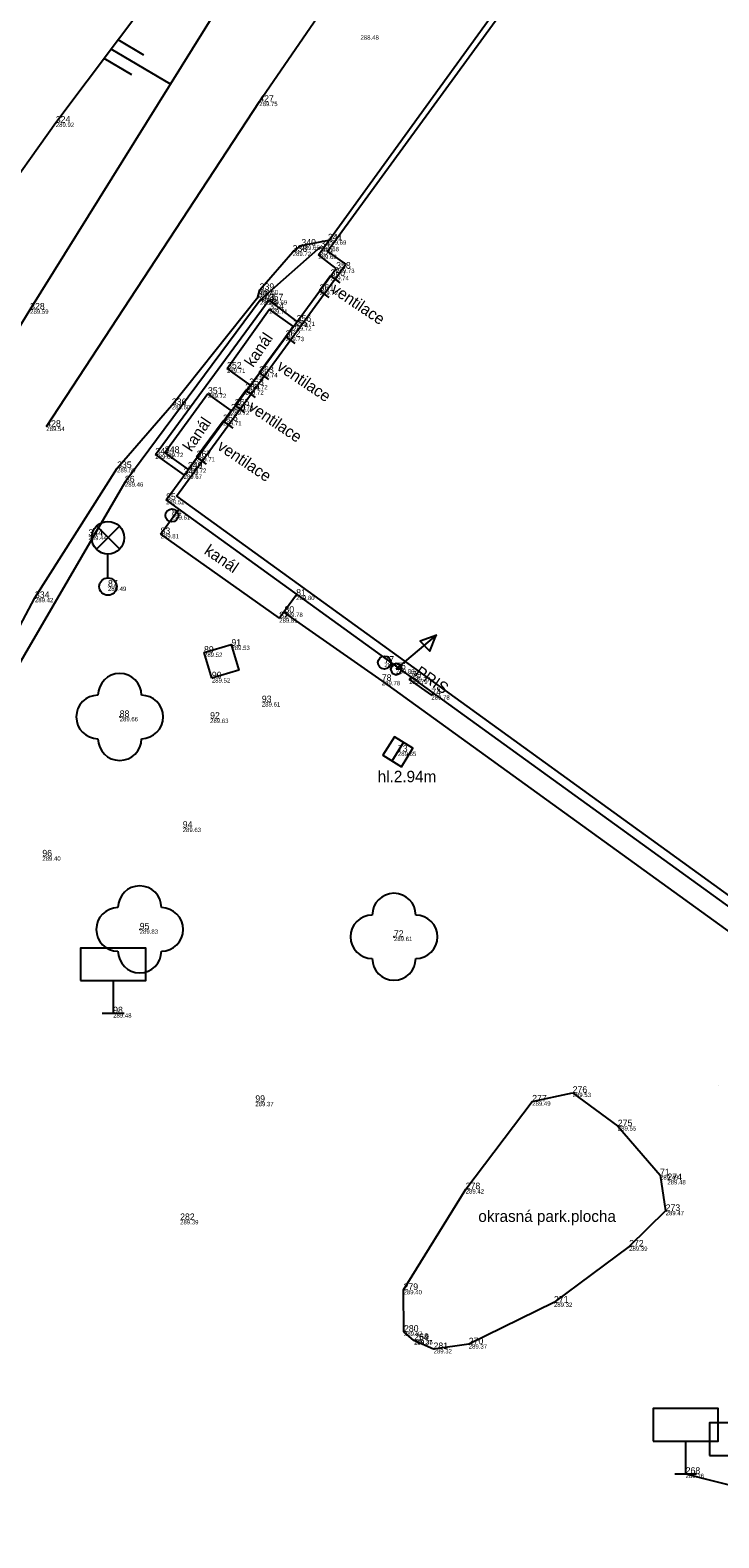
# Model space of a CAD drawing. Extents: x -805057 to -804930, y -994399 to -994240.
# Drawn here: x -805033.55 to -805017.71, y -994342.6 to -994307.89 of the extents above; entities that cross this region are included whole.
import ezdxf

# ---------------------------------------------------------------- set-up
doc = ezdxf.new("R2010")
doc.units = 0
for name, color, linetype in [('bod cislo', 7, 'Continuous'), ('bod pozice', 7, 'Continuous'), ('bod výška', 7, 'Continuous'), ('budova', 7, 'Continuous'), ('kanalizace', 7, 'Continuous'), ('Katastralni mapa', 7, 'Continuous'), ('komunikace', 7, 'Continuous'), ('lampa', 7, 'Continuous'), ('označník', 7, 'Continuous'), ('plot', 7, 'Continuous'), ('popis', 7, 'Continuous'), ('PRIS', 7, 'Continuous'), ('strom', 7, 'Continuous'), ('svah', 7, 'Continuous'), ('svod', 7, 'Continuous'), ('zemnění', 7, 'Continuous'), ('šachta hranatá', 7, 'Continuous'), ('šrafy', 7, 'Continuous')]:
    doc.layers.add(name, color=color, linetype=linetype)

msp = doc.modelspace()

# ---------------------------------------------------------------- linework, layer by layer
at = {"layer": 'bod pozice'}
for p, q in [((-805028.28, -994309.54), (-805028.28, -994309.54)), ((-805032.96, -994310.02), (-805032.96, -994310.02)), ((-805027.31, -994312.85), (-805027.31, -994312.85)), ((-805026.87, -994312.88), (-805026.87, -994312.88)), ((-805026.7, -994312.73), (-805026.7, -994312.73)), ((-805027.51, -994312.99), (-805027.51, -994312.99)), ((-805026.92, -994313.06), (-805026.92, -994313.06)), ((-805026.64, -994313.55), (-805026.64, -994313.55)), ((-805026.51, -994313.38), (-805026.51, -994313.38)), ((-805028.27, -994313.87), (-805028.27, -994313.87)), ((-805026.89, -994313.89), (-805026.89, -994313.89)), ((-805028.31, -994314.04), (-805028.31, -994314.04)), ((-805028.26, -994314.11), (-805028.26, -994314.11)), ((-805028.06, -994314.11), (-805028.06, -994314.11)), ((-805033.55, -994314.32), (-805033.55, -994314.32)), ((-805028.05, -994314.32), (-805028.05, -994314.32)), ((-805027.42, -994314.6), (-805027.42, -994314.6)), ((-805027.67, -994314.95), (-805027.67, -994314.95)), ((-805027.5, -994314.71), (-805027.5, -994314.71)), ((-805029.02, -994315.68), (-805029.02, -994315.68)), ((-805028.28, -994315.78), (-805028.28, -994315.78)), ((-805029.46, -994316.26), (-805029.46, -994316.26)), ((-805028.6, -994316.18), (-805028.6, -994316.18)), ((-805028.51, -994316.06), (-805028.51, -994316.06)), ((-805030.29, -994316.52), (-805030.29, -994316.52)), ((-805028.93, -994316.65), (-805028.93, -994316.65)), ((-805028.84, -994316.53), (-805028.84, -994316.53)), ((-805033.18, -994317.02), (-805033.18, -994317.02)), ((-805029.11, -994316.89), (-805029.11, -994316.89)), ((-805030.67, -994317.66), (-805030.67, -994317.66)), ((-805030.45, -994317.62), (-805030.45, -994317.62)), ((-805029.72, -994317.72), (-805029.72, -994317.72)), ((-805031.55, -994317.97), (-805031.55, -994317.97)), ((-805029.92, -994317.98), (-805029.92, -994317.98)), ((-805031.37, -994318.3), (-805031.37, -994318.3)), ((-805030.02, -994318.12), (-805030.02, -994318.12)), ((-805030.423, -994318.705), (-805030.423, -994318.705)), ((-805030.29, -994319.06), (-805030.29, -994319.06)), ((-805032.21, -994319.53), (-805032.21, -994319.53)), ((-805030.55, -994319.49), (-805030.55, -994319.49)), ((-805031.76, -994320.7), (-805031.76, -994320.7)), ((-805033.44, -994320.96), (-805033.44, -994320.96)), ((-805027.43, -994320.91), (-805027.43, -994320.91)), ((-805027.82, -994321.43), (-805027.82, -994321.43)), ((-805027.7, -994321.3), (-805027.7, -994321.3)), ((-805029.55, -994322.22), (-805029.55, -994322.22)), ((-805028.92, -994322.06), (-805028.92, -994322.06)), ((-805025.4, -994322.45), (-805025.4, -994322.45)), ((-805025.13, -994322.6), (-805025.13, -994322.6)), ((-805029.37, -994322.81), (-805029.37, -994322.81)), ((-805025.46, -994322.87), (-805025.46, -994322.87)), ((-805024.83, -994322.84), (-805024.83, -994322.84)), ((-805024.77, -994322.79), (-805024.77, -994322.79)), ((-805024.32, -994323.2), (-805024.32, -994323.2)), ((-805028.22, -994323.36), (-805028.22, -994323.36)), ((-805031.49, -994323.7), (-805031.49, -994323.7)), ((-805029.41, -994323.74), (-805029.41, -994323.74)), ((-805025.09, -994324.5), (-805025.09, -994324.5)), ((-805030.04, -994326.25), (-805030.04, -994326.25)), ((-805033.27, -994326.91), (-805033.27, -994326.91)), ((-805031.03, -994328.59), (-805031.03, -994328.59)), ((-805025.18, -994328.76), (-805025.18, -994328.76)), ((-805031.64, -994330.52), (-805031.64, -994330.52)), ((-805017.71, -994332.19), (-805017.71, -994332.19)), ((-805028.37, -994332.56), (-805028.37, -994332.56)), ((-805022, -994332.55), (-805022, -994332.55)), ((-805021.07, -994332.35), (-805021.07, -994332.35)), ((-805020.03, -994333.12), (-805020.03, -994333.12)), ((-805019.06, -994334.25), (-805019.06, -994334.25)), ((-805018.89, -994334.36), (-805018.89, -994334.36)), ((-805023.53, -994334.57), (-805023.53, -994334.57)), ((-805018.93, -994335.07), (-805018.93, -994335.07)), ((-805030.1, -994335.28), (-805030.1, -994335.28)), ((-805019.77, -994335.89), (-805019.77, -994335.89)), ((-805024.96, -994336.89), (-805024.96, -994336.89)), ((-805021.5, -994337.18), (-805021.5, -994337.18)), ((-805024.95, -994337.85), (-805024.95, -994337.85)), ((-805024.72, -994338.05), (-805024.72, -994338.05)), ((-805024.71, -994338.04), (-805024.71, -994338.04)), ((-805023.46, -994338.14), (-805023.46, -994338.14)), ((-805024.27, -994338.25), (-805024.27, -994338.25)), ((-805018.47, -994341.12), (-805018.47, -994341.12))]:
    msp.add_line(p, q, dxfattribs=at)
at = {"layer": 'budova'}
for p, q in [((-805026.92, -994313.06), (-805021.089, -994305.009)), ((-805026.51, -994313.38), (-805026.92, -994313.06)), ((-805030.423, -994318.705), (-805026.51, -994313.38)), ((-804995.51, -994343.96), (-805030.423, -994318.706))]:
    msp.add_line(p, q, dxfattribs=at)
at = {"layer": 'kanalizace'}
msp.add_line((-805025.222, -994324.712), (-805024.958, -994324.288), dxfattribs=at)
msp.add_lwpolyline([(-805025.01, -994324.845), (-805024.744, -994324.421), (-805025.17, -994324.155), (-805025.435, -994324.579)], close=True, dxfattribs=at)
at = {"layer": 'Katastralni mapa'}
for points in [[(-805026.71, -994312.98), (-805021.06, -994305.21)], [(-805026.29, -994313.28), (-805026.71, -994312.98)], [(-805030.18, -994318.62), (-805026.29, -994313.28)], [(-805030.18, -994318.62), (-804995.54, -994343.69)]]:
    msp.add_lwpolyline(points, dxfattribs=at)
at = {"layer": 'komunikace'}
for p, q in [((-805028.28, -994309.54), (-805022, -994300.4)), ((-805033.55, -994314.32), (-805029.27, -994307.45)), ((-805028.28, -994309.54), (-805033.18, -994317.02)), ((-805027.51, -994312.99), (-805027.31, -994312.85)), ((-805027.31, -994312.85), (-805026.678, -994312.726)), ((-805028.27, -994313.87), (-805027.51, -994312.99)), ((-805028.31, -994314.04), (-805028.27, -994313.87)), ((-805030.67, -994317.66), (-805028.06, -994314.11)), ((-805030.29, -994316.52), (-805028.31, -994314.04)), ((-805028.06, -994314.11), (-805027.411, -994314.607)), ((-805036.691, -994319.454), (-805033.55, -994314.32)), ((-805031.55, -994317.97), (-805030.29, -994316.52)), ((-805030.002, -994318.132), (-805030.67, -994317.66)), ((-805033.44, -994320.96), (-805031.55, -994317.97)), ((-805030.55, -994319.49), (-805030.133, -994318.916)), ((-805030.55, -994319.49), (-805027.82, -994321.43)), ((-805036.91, -994327.47), (-805033.44, -994320.96)), ((-805027.82, -994321.43), (-805027.42, -994320.878)), ((-805027.7, -994321.3), (-805025.46, -994322.87)), ((-805025.46, -994322.87), (-805005.97, -994336.96))]:
    msp.add_line(p, q, dxfattribs=at)
at = {"layer": 'lampa'}
for p, q in [((-805032.024, -994319.838), (-805031.496, -994319.31)), ((-805031.488, -994319.835), (-805032.016, -994319.306)), ((-805031.76, -994320.5), (-805031.76, -994319.95))]:
    msp.add_line(p, q, dxfattribs=at)
for centre, radius in [((-805031.76, -994319.575), 0.375), ((-805031.76, -994320.7), 0.2)]:
    msp.add_circle(centre, radius, dxfattribs=at)
at = {"layer": 'označník'}
for p, q in [((-805031.64, -994329.77), (-805031.64, -994330.52)), ((-805031.89, -994330.52), (-805031.39, -994330.52)), ((-805018.47, -994340.37), (-805018.47, -994341.12)), ((-805018.72, -994341.12), (-805018.22, -994341.12)), ((-805018.47, -994341.12), (-805017.17, -994341.45))]:
    msp.add_line(p, q, dxfattribs=at)
for points in [[(-805032.39, -994329.77), (-805030.89, -994329.77), (-805030.89, -994329.02), (-805032.39, -994329.02)], [(-805019.22, -994340.37), (-805017.72, -994340.37), (-805017.72, -994339.62), (-805019.22, -994339.62)], [(-805017.92, -994340.7), (-805016.42, -994340.7), (-805016.42, -994339.95), (-805017.92, -994339.95)]]:
    msp.add_lwpolyline(points, close=True, dxfattribs=at)
at = {"layer": 'plot'}
for p, q in [((-805026.87, -994312.88), (-805028.26, -994314.11)), ((-805028.26, -994314.11), (-805031.37, -994318.3)), ((-805031.37, -994318.3), (-805035.75, -994325.82))]:
    msp.add_line(p, q, dxfattribs=at)
at = {"layer": 'PRIS'}
for p, q in [((-805024.83, -994322.84), (-805024.787, -994322.782)), ((-805024.83, -994322.84), (-805024.32, -994323.2)), ((-805024.32, -994323.2), (-805024.282, -994323.148))]:
    msp.add_line(p, q, dxfattribs=at)
at = {"layer": 'strom'}
for p, q in [((-805023.53, -994334.57), (-805022, -994332.55)), ((-805022, -994332.55), (-805021.07, -994332.35)), ((-805021.07, -994332.35), (-805020.03, -994333.12)), ((-805020.03, -994333.12), (-805019.06, -994334.25)), ((-805019.06, -994334.25), (-805018.93, -994335.07)), ((-805024.96, -994336.89), (-805023.53, -994334.57)), ((-805018.93, -994335.07), (-805019.77, -994335.89)), ((-805019.77, -994335.89), (-805021.5, -994337.18)), ((-805024.95, -994337.85), (-805024.96, -994336.89)), ((-805021.5, -994337.18), (-805023.46, -994338.14)), ((-805024.72, -994338.05), (-805024.95, -994337.85)), ((-805024.27, -994338.25), (-805024.72, -994338.05)), ((-805023.46, -994338.14), (-805024.27, -994338.25))]:
    msp.add_line(p, q, dxfattribs=at)
for centre in [(-805031.49, -994323.7), (-805031.03, -994328.59), (-805025.18, -994328.76)]:
    msp.add_circle(centre, 0.0005, dxfattribs=at)
for centre, start, end in [((-805031.49, -994323.2), 0, 180), ((-805031.99, -994323.7), 90, 270), ((-805030.99, -994323.7), 270, 90), ((-805031.49, -994324.2), 180, 360), ((-805031.03, -994328.09), 0, 180), ((-805025.18, -994328.26), 0, 180), ((-805031.53, -994328.59), 90, 270), ((-805030.53, -994328.59), 270, 90), ((-805025.68, -994328.76), 90, 270), ((-805024.68, -994328.76), 270, 90), ((-805031.03, -994329.09), 180, 360), ((-805025.18, -994329.26), 180, 360)]:
    msp.add_arc(centre, 0.5, start, end, dxfattribs=at)
at = {"layer": 'svah'}
for p, q in [((-805032.96, -994310.02), (-805030.42, -994306.63)), ((-805036.52, -994315.02), (-805032.96, -994310.02))]:
    msp.add_line(p, q, dxfattribs=at)
at = {"layer": 'svod'}
for centre in [(-805030.29, -994319.06), (-805025.4, -994322.45)]:
    msp.add_circle(centre, 0.15, dxfattribs=at)
at = {"layer": 'zemnění'}
msp.add_line((-805025.13, -994322.6), (-805024.246, -994321.859), dxfattribs=at)
msp.add_lwpolyline([(-805024.194, -994321.82), (-805024.574, -994321.956), (-805024.358, -994322.184), (-805024.206, -994321.821)], close=True, dxfattribs=at)
msp.add_lwpolyline([(-805024.996, -994322.6), (-805025.035, -994322.505), (-805025.13, -994322.466), (-805025.225, -994322.505), (-805025.264, -994322.6), (-805025.225, -994322.695), (-805025.13, -994322.734), (-805025.035, -994322.695), (-805024.996, -994322.6), (-805025.13, -994322.6)], dxfattribs=at)
at = {"layer": 'šachta hranatá'}
for p, q in [((-805026.64, -994313.55), (-805026.89, -994313.89)), ((-805026.64, -994313.55), (-805026.429, -994313.705)), ((-805026.89, -994313.89), (-805026.679, -994314.045)), ((-805027.67, -994314.95), (-805028.28, -994315.78)), ((-805027.67, -994314.95), (-805027.459, -994315.105)), ((-805028.28, -994315.78), (-805028.069, -994315.935)), ((-805028.589, -994316.188), (-805028.84, -994316.53)), ((-805028.6, -994316.18), (-805028.372, -994316.347)), ((-805028.84, -994316.53), (-805028.624, -994316.689)), ((-805029.11, -994316.89), (-805029.72, -994317.72)), ((-805029.11, -994316.89), (-805028.89, -994317.052)), ((-805029.72, -994317.72), (-805029.5, -994317.882))]:
    msp.add_line(p, q, dxfattribs=at)
for points in [[(-805029.02, -994315.68), (-805028.05, -994314.32), (-805027.501, -994314.712), (-805028.471, -994316.072)], [(-805029.46, -994316.26), (-805030.45, -994317.62), (-805029.918, -994318.007), (-805028.928, -994316.647)], [(-805029.37, -994322.81), (-805029.55, -994322.22), (-805028.929, -994322.031), (-805028.749, -994322.621)]]:
    msp.add_lwpolyline(points, close=True, dxfattribs=at)
at = {"layer": 'šrafy'}
for p, q in [((-805030.322, -994309.138), (-805031.69, -994308.325)), ((-805030.934, -994308.464), (-805031.529, -994308.111)), ((-805031.208, -994308.923), (-805031.851, -994308.54))]:
    msp.add_line(p, q, dxfattribs=at)

# ---------------------------------------------------------------- texts
at = {"layer": 'bod cislo'}
for s, p in [('427    ', (-805028.28, -994309.54)), ('324    ', (-805032.96, -994310.02)), ('338    ', (-805027.51, -994312.99)), ('340    ', (-805027.31, -994312.85)), ('342    ', (-805026.87, -994312.88)), ('341    ', (-805026.7, -994312.73)), ('359    ', (-805026.92, -994313.06)), ('358    ', (-805026.51, -994313.38)), ('360    ', (-805026.64, -994313.55)), ('337    ', (-805028.31, -994314.04)), ('339    ', (-805028.27, -994313.87)), ('361    ', (-805026.89, -994313.89)), ('328    ', (-805033.55, -994314.32)), ('343    ', (-805028.26, -994314.11)), ('357    ', (-805028.06, -994314.11)), ('354    ', (-805028.05, -994314.32)), ('355    ', (-805027.5, -994314.71)), ('356    ', (-805027.42, -994314.6)), ('362    ', (-805027.67, -994314.95)), ('352    ', (-805029.02, -994315.68)), ('363    ', (-805028.28, -994315.78)), ('353    ', (-805028.51, -994316.06)), ('351    ', (-805029.46, -994316.26)), ('364    ', (-805028.6, -994316.18)), ('336    ', (-805030.29, -994316.52)), ('350    ', (-805028.93, -994316.65)), ('365    ', (-805028.84, -994316.53)), ('428    ', (-805033.18, -994317.02)), ('366    ', (-805029.11, -994316.89)), ('347    ', (-805030.67, -994317.66)), ('348    ', (-805030.45, -994317.62)), ('367    ', (-805029.72, -994317.72)), ('335    ', (-805031.55, -994317.97)), ('346    ', (-805030.02, -994318.12)), ('349    ', (-805029.92, -994317.98)), ('86    ', (-805031.37, -994318.3)), ('85    ', (-805030.423, -994318.705)), ('84    ', (-805030.29, -994319.06)), ('344    ', (-805032.21, -994319.53)), ('83    ', (-805030.55, -994319.49)), ('334    ', (-805033.44, -994320.96)), ('87    ', (-805031.76, -994320.7)), ('81    ', (-805027.43, -994320.91)), ('80    ', (-805027.7, -994321.3)), ('82    ', (-805027.82, -994321.43)), ('91    ', (-805028.92, -994322.06)), ('89    ', (-805029.55, -994322.22)), ('77    ', (-805025.4, -994322.45)), ('76    ', (-805025.13, -994322.6)), ('90    ', (-805029.37, -994322.81)), ('78    ', (-805025.46, -994322.87)), ('75    ', (-805024.83, -994322.84)), ('79    ', (-805024.77, -994322.79)), ('93    ', (-805028.22, -994323.36)), ('74    ', (-805024.32, -994323.2)), ('88    ', (-805031.49, -994323.7)), ('92    ', (-805029.41, -994323.74)), ('73    ', (-805025.09, -994324.5)), ('94    ', (-805030.04, -994326.25)), ('96    ', (-805033.27, -994326.91)), ('95    ', (-805031.03, -994328.59)), ('72    ', (-805025.18, -994328.76)), ('98    ', (-805031.64, -994330.52)), ('276    ', (-805021.07, -994332.35)), ('99    ', (-805028.37, -994332.56)), ('277    ', (-805022, -994332.55)), ('275    ', (-805020.03, -994333.12)), ('71    ', (-805019.06, -994334.25)), ('274    ', (-805018.89, -994334.36)), ('278    ', (-805023.53, -994334.57)), ('273    ', (-805018.93, -994335.07)), ('282    ', (-805030.1, -994335.28)), ('272    ', (-805019.77, -994335.89)), ('279    ', (-805024.96, -994336.89)), ('271    ', (-805021.5, -994337.18)), ('280    ', (-805024.95, -994337.85)), ('254    ', (-805024.72, -994338.05)), ('269    ', (-805024.71, -994338.04)), ('281    ', (-805024.27, -994338.25)), ('270    ', (-805023.46, -994338.14)), ('268    ', (-805018.47, -994341.12))]:
    msp.add_text(s, height=0.15, dxfattribs=at).set_placement(p)
at = {"layer": 'bod výška'}
for s, p in [('288.48  ', (-805025.95, -994308.11)), ('289.75  ', (-805028.28, -994309.64)), ('289.92  ', (-805032.96, -994310.12)), ('289.65  ', (-805027.31, -994312.95)), ('289.68  ', (-805026.87, -994312.98)), ('289.69  ', (-805026.7, -994312.83)), ('289.72  ', (-805027.51, -994313.09)), ('289.68  ', (-805026.92, -994313.16)), ('289.74  ', (-805026.64, -994313.65)), ('289.73  ', (-805026.51, -994313.48)), ('289.60  ', (-805028.27, -994313.97)), ('289.72  ', (-805026.89, -994313.99)), ('289.59  ', (-805028.31, -994314.14)), ('289.59  ', (-805028.26, -994314.21)), ('289.69  ', (-805028.06, -994314.21)), ('289.59  ', (-805033.55, -994314.42)), ('289.71  ', (-805028.05, -994314.42)), ('289.71  ', (-805027.42, -994314.7)), ('289.73  ', (-805027.67, -994315.05)), ('289.72  ', (-805027.5, -994314.81)), ('289.71  ', (-805029.02, -994315.78)), ('289.74  ', (-805028.28, -994315.88)), ('289.72  ', (-805029.46, -994316.36)), ('289.72  ', (-805028.6, -994316.28)), ('289.72  ', (-805028.51, -994316.16)), ('289.60  ', (-805030.29, -994316.62)), ('289.72  ', (-805028.93, -994316.75)), ('289.73  ', (-805028.84, -994316.63)), ('289.54  ', (-805033.18, -994317.12)), ('289.71  ', (-805029.11, -994316.99)), ('289.62  ', (-805030.67, -994317.76)), ('289.72  ', (-805030.45, -994317.72)), ('289.71  ', (-805029.72, -994317.82)), ('289.50  ', (-805031.55, -994318.07)), ('289.72  ', (-805029.92, -994318.08)), ('289.46  ', (-805031.37, -994318.4)), ('289.67  ', (-805030.02, -994318.22)), ('289.52  ', (-805030.423, -994318.805)), ('289.61  ', (-805030.29, -994319.16)), ('289.44  ', (-805032.21, -994319.63)), ('289.81  ', (-805030.55, -994319.59)), ('289.49  ', (-805031.76, -994320.8)), ('289.42  ', (-805033.44, -994321.06)), ('289.80  ', (-805027.43, -994321.01)), ('289.81  ', (-805027.82, -994321.53)), ('289.78  ', (-805027.7, -994321.4)), ('289.52  ', (-805029.55, -994322.32)), ('289.53  ', (-805028.92, -994322.16)), ('289.80  ', (-805025.4, -994322.55)), ('289.80  ', (-805025.13, -994322.7)), ('289.52  ', (-805029.37, -994322.91)), ('289.78  ', (-805025.46, -994322.97)), ('289.79  ', (-805024.83, -994322.94)), ('289.77  ', (-805024.77, -994322.89)), ('289.78  ', (-805024.32, -994323.3)), ('289.61  ', (-805028.22, -994323.46)), ('289.66  ', (-805031.49, -994323.8)), ('289.63  ', (-805029.41, -994323.84)), ('289.65  ', (-805025.09, -994324.6)), ('289.63  ', (-805030.04, -994326.35)), ('289.40  ', (-805033.27, -994327.01)), ('289.83  ', (-805031.03, -994328.69)), ('289.61  ', (-805025.18, -994328.86)), ('289.48  ', (-805031.64, -994330.62)), ('289.37  ', (-805028.37, -994332.66)), ('289.49  ', (-805022, -994332.65)), ('289.53  ', (-805021.07, -994332.45)), ('289.55  ', (-805020.03, -994333.22)), ('289.49  ', (-805019.06, -994334.35)), ('289.48  ', (-805018.89, -994334.46)), ('289.42  ', (-805023.53, -994334.67)), ('289.47  ', (-805018.93, -994335.17)), ('289.39  ', (-805030.1, -994335.38)), ('289.39  ', (-805019.77, -994335.99)), ('289.40  ', (-805024.96, -994336.99)), ('289.32  ', (-805021.5, -994337.28)), ('289.37  ', (-805024.95, -994337.95)), ('289.37  ', (-805024.72, -994338.15)), ('289.35  ', (-805024.71, -994338.14)), ('289.37  ', (-805023.46, -994338.24)), ('289.32  ', (-805024.27, -994338.35)), ('289.26  ', (-805018.47, -994341.22))]:
    msp.add_text(s, height=0.1, dxfattribs=at).set_placement(p)
at = {"layer": 'popis'}
for s, rotation, p in [('ventilace', 326.0249, (-805026.653, -994313.912)), ('kanál', 56.0249, (-805028.422, -994315.668)), ('ventilace', 326.0249, (-805027.898, -994315.688)), ('ventilace', 326.0249, (-805028.562, -994316.622)), ('kanál', 56.0249, (-805029.841, -994317.613)), ('ventilace', 326.0249, (-805029.267, -994317.526)), ('kanál', 326.0249, (-805029.567, -994319.93)), ('PRIS', 326.0249, (-805024.719, -994322.728))]:
    msp.add_text(s, height=0.2629, rotation=rotation, dxfattribs=at).set_placement(p)
for s, height, p in [('hl.2.94m', 0.2629, (-805025.555, -994325.202)), ('okrasná park.plocha', 0.26289, (-805023.24, -994335.323))]:
    msp.add_text(s, height=height, dxfattribs=at).set_placement(p)

doc.saveas('drawing.dxf')
